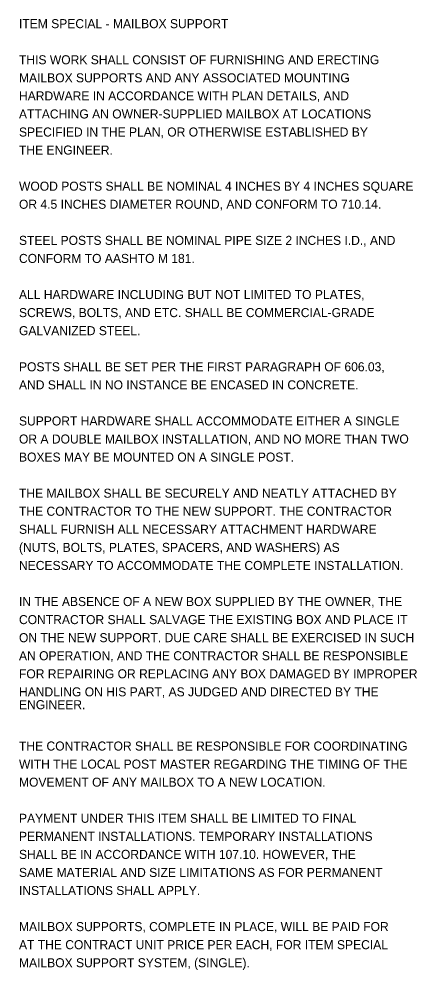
# Model space of a CAD drawing. Extents: x -20.9 to 41.8, y -2.3 to 41.6.
# Drawn here: x 4.1 to 10.27, y 26.85 to 41.59 of the extents above; entities that cross this region are included whole.
import ezdxf

# ---------------------------------------------------------------- set-up
doc = ezdxf.new("R2010")
doc.units = 0
doc.layers.add('SH_Border', color=7, linetype='Continuous')

msp = doc.modelspace()

# ---------------------------------------------------------------- texts
at = {"layer": 'SH_Border'}
for s, p in [('ITEM SPECIAL - MAILBOX SUPPORT', (4.095, 41.452)), ('THIS WORK SHALL CONSIST OF FURNISHING AND ERECTING', (4.095, 40.892)), ('MAILBOX SUPPORTS AND ANY ASSOCIATED MOUNTING', (4.095, 40.612)), ('HARDWARE IN ACCORDANCE WITH PLAN DETAILS, AND', (4.095, 40.332)), ('ATTACHING AN OWNER-SUPPLIED MAILBOX AT LOCATIONS', (4.095, 40.052)), ('SPECIFIED IN THE PLAN, OR OTHERWISE ESTABLISHED BY', (4.095, 39.772)), ('THE ENGINEER.', (4.095, 39.492)), ('WOOD POSTS SHALL BE NOMINAL 4 INCHES BY 4 INCHES SQUARE', (4.095, 38.932)), ('OR 4.5 INCHES DIAMETER ROUND, AND CONFORM TO 710.14.', (4.095, 38.652)), ('STEEL POSTS SHALL BE NOMINAL PIPE SIZE 2 INCHES I.D., AND', (4.095, 38.092)), ('CONFORM TO AASHTO M 181.', (4.095, 37.812)), ('ALL HARDWARE INCLUDING BUT NOT LIMITED TO PLATES,', (4.095, 37.252)), ('SCREWS, BOLTS, AND ETC. SHALL BE COMMERCIAL-GRADE', (4.095, 36.972)), ('GALVANIZED STEEL.', (4.095, 36.692)), ('POSTS SHALL BE SET PER THE FIRST PARAGRAPH OF 606.03,', (4.095, 36.132)), ('AND SHALL IN NO INSTANCE BE ENCASED IN CONCRETE.', (4.095, 35.852)), ('SUPPORT HARDWARE SHALL ACCOMMODATE EITHER A SINGLE', (4.095, 35.292)), ('OR A DOUBLE MAILBOX INSTALLATION, AND NO MORE THAN TWO', (4.095, 35.012)), ('BOXES MAY BE MOUNTED ON A SINGLE POST.', (4.095, 34.732)), ('THE MAILBOX SHALL BE SECURELY AND NEATLY ATTACHED BY', (4.095, 34.172)), ('THE CONTRACTOR TO THE NEW SUPPORT. THE CONTRACTOR', (4.095, 33.892)), ('SHALL FURNISH ALL NECESSARY ATTACHMENT HARDWARE', (4.095, 33.612)), ('(NUTS, BOLTS, PLATES, SPACERS, AND WASHERS) AS', (4.095, 33.332)), ('NECESSARY TO ACCOMMODATE THE COMPLETE INSTALLATION.', (4.095, 33.052)), ('IN THE ABSENCE OF A NEW BOX SUPPLIED BY THE OWNER, THE', (4.095, 32.492)), ('CONTRACTOR SHALL SALVAGE THE EXISTING BOX AND PLACE IT', (4.095, 32.212)), ('ON THE NEW SUPPORT. DUE CARE SHALL BE EXERCISED IN SUCH', (4.095, 31.932)), ('AN OPERATION, AND THE CONTRACTOR SHALL BE RESPONSIBLE', (4.095, 31.652)), ('FOR REPAIRING OR REPLACING ANY BOX DAMAGED BY IMPROPER', (4.095, 31.372)), ('HANDLING ON HIS PART, AS JUDGED AND DIRECTED BY THE', (4.095, 31.092)), ('ENGINEER.', (4.095, 30.893)), ('THE CONTRACTOR SHALL BE RESPONSIBLE FOR COORDINATING', (4.095, 30.252)), ('WITH THE LOCAL POST MASTER REGARDING THE TIMING OF THE', (4.095, 29.972)), ('MOVEMENT OF ANY MAILBOX TO A NEW LOCATION.', (4.095, 29.692)), ('PAYMENT UNDER THIS ITEM SHALL BE LIMITED TO FINAL', (4.095, 29.132)), ('PERMANENT INSTALLATIONS. TEMPORARY INSTALLATIONS', (4.095, 28.852)), ('SHALL BE IN ACCORDANCE WITH 107.10. HOWEVER, THE', (4.095, 28.572)), ('SAME MATERIAL AND SIZE LIMITATIONS AS FOR PERMANENT', (4.095, 28.292)), ('INSTALLATIONS SHALL APPLY.', (4.095, 28.012)), ('MAILBOX SUPPORTS, COMPLETE IN PLACE, WILL BE PAID FOR', (4.095, 27.452)), ('AT THE CONTRACT UNIT PRICE PER EACH, FOR ITEM SPECIAL', (4.095, 27.172)), ('MAILBOX SUPPORT SYSTEM, (SINGLE).', (4.095, 26.892))]:
    msp.add_text(s, height=0.14, dxfattribs=at).set_placement(p)

doc.saveas('drawing.dxf')
